// Mitsubishi GX Works2 project: 6亮+1不亮循环（循环嵌套位移）   PLC: FX3U/FX3UC

PROGRAM MAIN
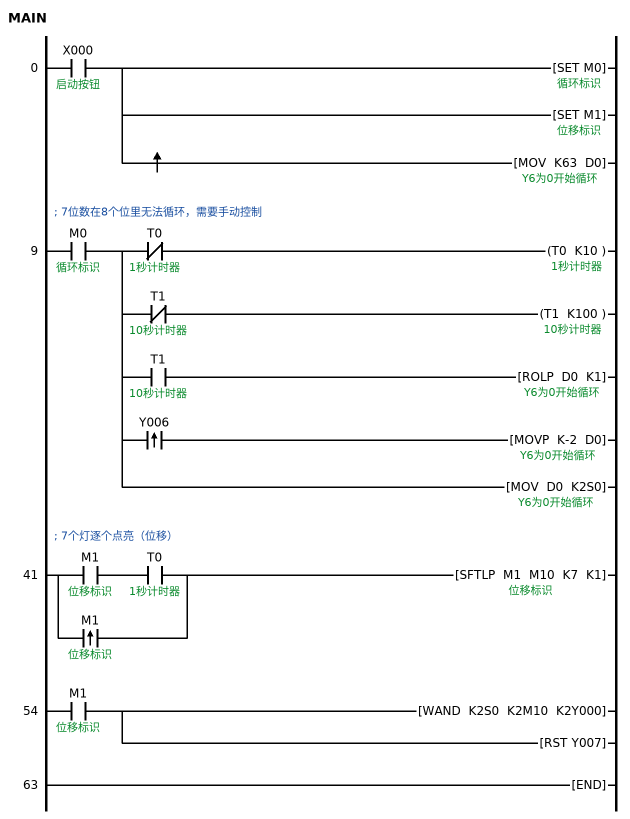
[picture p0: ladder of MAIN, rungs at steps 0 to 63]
0     LD      X000  ; 启动按钮
      SET     M0  ; 循环标识
      SET     M1  ; 位移标识
      MEP
      MOV     K63 D0  ; Y6为0开始循环
; 7位数在8个位里无法循环，需要手动控制
9     LD      M0  ; 循环标识
      MPS
      ANI     T0  ; 1秒计时器
      OUT     T0 K10  ; 1秒计时器
      MRD
      ANI     T1  ; 10秒计时器
      OUT     T1 K100  ; 10秒计时器
      MRD
      AND     T1  ; 10秒计时器
      ROLP    D0 K1
      MRD
      ANDP    Y006
      MOVP    K-2 D0
        [note] Y6点亮后重置循环
      MPP
      MOV     D0 K2S0
        [note] 存储循环结果
; 7个灯逐个点亮（位移）
41    LD      M1  ; 位移标识
      AND     T0  ; 1秒计时器
      ORP     M1  ; 位移标识
      SFTLP   M1 M10 K7 K1
54    LD      M1  ; 位移标识
      WAND    K2S0 K2M10 K2Y000
        [note] 对比循环和位移数据得出结果到Y
      RST     Y007
        [note] Y7永远不亮
63    END
END_PROGRAM
